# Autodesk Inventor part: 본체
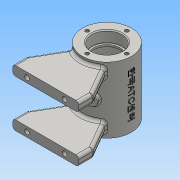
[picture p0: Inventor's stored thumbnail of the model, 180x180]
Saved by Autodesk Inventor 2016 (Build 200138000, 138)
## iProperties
Created: 2018-05
Part Number: 본체
Material: 일반
Document SubType Name: Modeling
Designer: Administrator
Density: 1 g/cm^3
Appearance: 기본값
Author: Administrator
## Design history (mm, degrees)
sketch "스케치1"
  geometry: L1 (0, 0)-(0, -70); L2 (0, 0)-(26, 0); L3 (26, 0)-(26, -70); L4 (26, -70)-(0, -70)
  constraints: 8 end point, 2 vertical, 1 horizontal
  dimensions: "d0" = 70 distance of L1.start L1.end; "d1" = 70 distance of L2.end L3.end; "d2" = 52 diameter of L3 L1
revolve "회전1" sketch "스케치1" stored, may be unused: angle "d3" = 90 deg
node "작업 평면1"
node "작업 평면2"
node "작업 평면3"
sketch "스케치2"
  geometry: L1 (0, 0)-(0, -103.85); L2 (-35, -65)-(35, -65); L3 (0, 0)-(20.203, 0); L4 (35, -65)-(35, -50); L5 (35, -50)-(17.325, -19.386); L6 (-35, -65)-(-35, -50); L7 (-35, -50)-(-17.325, -19.386); A1 r 26 centre (0, 0) between (17.325, -19.386) and (-17.325, -19.386) reference; A2 r 26 centre (0, 0) between (-17.325, -19.386) and (17.325, -19.386); 3 further points
  constraints: 14 end point, 4 point on circle, 3 vertical, 2 horizontal, 2 point on line, 1 centre point, 1 midpoint
  dimensions: "d8" = 65 vertical distance of L2.end L3.end; "d9" = 70 distance of L2.start L2.end; "d10" = 15 distance of L2.end L4.end; "d11" = 30 deg angle of L4 L5; "d12" = 15 distance of L2.start L6.end; "d13" = 30 deg angle of L6 L7
extrude "돌출1" join sketch "스케치2" distance "d14" = 10; taper "d15" = 0 deg
sketch "스케치3"
  geometry: L1 (0, 0)-(70, 0) reference; L2 (70, 0)-(70, 10) reference; L3 (0, 10)-(70, 10) reference; L4 (0, 0)-(0, 10) reference; L5 (9, 15)-(61, 15) reference; L6 (9, -55)-(61, -55) reference; L7 (0, -40)-(70, -40) reference; L8 (0, -50)-(70, -50) reference; L9 (35, 15)-(35, -55); L10 (55, 22.355)-(55, -60.469); L11 (15, 19.937)-(15, -63.895); L12 (77.307, 5)-(-12.167, 5); L13 (77.307, -45)-(-22.445, -45); C1 r 2.5 at (15, 5); C2 r 2.5 at (55, 5); C3 r 2.5 at (55, -45); C4 r 2.5 at (15, -45)
  constraints: 10 end point, 8 point on line, 4 centre point, 2 horizontal, 2 vertical, 1 midpoint
  dimensions: "d16" = 20 horizontal distance of L10.end L9.end; "d17" = 20 horizontal distance of L11.end L9.end; "d18" = 5 distance between parallel lines of L3 L12; "d19" = 5 distance between parallel lines of L8 L13; "d20" = 5 diameter of C1; "d21" = 5 diameter of C2; "d22" = 5 diameter of C3; "d23" = 5 diameter of C4
hole "구멍1" sketch "스케치3" at (15, 5), (55, 5), (55, -45), (15, -45) diameter "d24" = 5; stored, may be unused: countersink angle "d28" = 90 deg, drill point angle "d30" = 118 deg; dims "d25" = 6, "d26" = 4, "d27" = 2, "d29" = 10
feature "스레드1" dims "d31" = 8, "d32" = 0
feature "스레드2" dims "d33" = 8, "d34" = 0
feature "스레드3" dims "d35" = 8, "d36" = 0
feature "스레드4" dims "d37" = 8, "d38" = 0
node "작업 평면4"
sketch "스케치4"
  geometry: L1 (3.602, 24.887)-(3.602, -24.887); L2 (3.602, -24.887)-(-3.602, -24.887); L3 (-3.602, -24.887)-(-3.602, 24.887); L4 (-3.602, 24.887)-(3.602, 24.887); L5 (-19.386, -20)-(-19.386, -30) reference; L6 (-19.386, -30)-(-19.386, -30) reference; L7 (-19.386, -30)-(-19.386, -20) reference; L8 (-19.386, -20)-(-19.386, -20) reference; L9 (-19.386, 30)-(-19.386, 20) reference; L10 (-19.386, 20)-(-19.386, 20) reference; L11 (-19.386, 20)-(-19.386, 30) reference; L12 (-19.386, 30)-(-19.386, 30) reference; L13 (-26, 35)-(26, 35) reference; L14 (-26, -35)-(26, -35) reference; L15 (26, 35)-(26, -35) reference; L16 (26, 0)-(0, 0); L17 (-26, 35)-(-26, -35) reference; 1 further point
  constraints: 2 end point, 1 midpoint, 2 other
feature "엠보싱1" sketch "스케치4" dims "d8" = 65, "d9" = 70, "d10" = 15, "d11" = 30 deg, "d12" = 15, "d13" = 30 deg, "d39" = 0.5, "d40" = 0
node "작업 평면6"
  node "작업 평면5"
sketch "스케치5"
  geometry: L1 (-26, 35)-(-26, -35) reference; L2 (-26, -35)-(26, -35) reference; L3 (-26, 35)-(26, 35) reference; L4 (26, 35)-(26, -35) reference; L5 (0, -35)-(0, 0); C1 r 5 at (0, 0); 1 further point
  constraints: 2 end point, 1 centre point, 1 coincident, 1 midpoint
  dimensions: "d42" = 10 diameter of C1
extrude "돌출2" join sketch "스케치5" distance "d43" = 20; taper "d44" = 0 deg
node "작업 평면7"
sketch "스케치6"
  geometry: L1 (5, 29)-(-5, 29) reference; L2 (0, 29)-(0, -23.345); L3 (0, 0)-(-8.893, -24.432); L4 (-4.593, -29.207)-(-9.924, -27.267); L5 (-4.593, -29.207)-(-3.347, -25.784); L6 (-9.924, -27.267)-(-8.893, -24.432); A1 r 26 centre (0, 0) between (17.325, -19.386) and (-17.325, -19.386) reference; A2 r 26 centre (0, 0) between (-17.325, -19.386) and (17.325, -19.386) reference; 1 further point
  constraints: 10 end point, 3 point on circle, 1 midpoint, 1 perpendicular, 1 point on line, 1 vertical
  dimensions: "d47" = 20 deg angle of L2 L3; "d54" = 27.26656 vertical distance of L4.end point (0, 0); "d57" = 11.3474 diameter of L5 L3
revolve "회전2" sketch "스케치6" stored, may be unused: angle "d58" = 90 deg
node "작업 평면8"
sketch "스케치8"
  geometry: L1 (-15, 39)-(-15, 91) reference; L2 (55, 39)-(55, 91) reference; L3 (-15, 65)-(55, 65); L4 (-15, 81)-(-3.3, 81); L5 (-3, 80.7)-(-3, 79); L6 (-3, 79)-(-1, 79); L7 (-1, 79)-(-1, 83); L8 (2, 86)-(38, 86); L9 (55, 81)-(43.3, 81); L10 (43, 80.7)-(43, 79); L11 (43, 79)-(41, 79); L12 (41, 83)-(41, 79); A1 r 0.3 centre (-3.3, 80.7) between (-3, 80.7) and (-3.3, 81); A2 r 0.3 centre (43.3, 80.7) between (43.3, 81) and (43, 80.7); A3 r 3 centre (38, 83) between (41, 83) and (38, 86); A4 r 3 centre (2, 83) between (2, 86) and (-1, 83); 4 further points
  constraints: 20 end point, 10 point on line, 8 point on circle, 8 tangent, 4 centre point, 3 perpendicular, 3 vertical, 2 equal radius, 2 horizontal, 1 midpoint
  dimensions: "d59" = 12 distance of L4.start point (-3, 81); "d60" = 32 diameter of L4 L3; "d61" = 2 distance of L5.end L6.end; "d62" = 28 diameter of L6 L3; "d63" = 42 diameter of L8 L3; "d64" = 42 distance of point (-1, 86) point (41, 86); "d65" = 12 distance of L9.start point (43, 81); "d66" = 32 diameter of L9 L3; "d67" = 2 distance of L10.end L11.end; "d68" = 28 diameter of L11 L3; "d69" = 0.3 radius of A1; "d70" = 3 radius of A3
revolve "회전3" sketch "스케치8" stored, may be unused: angle "d71" = 90 deg
chamfer "모따기1" distance "d72" = 1; stored, may be unused: second distance "d73" = 2, angle "d74" = 45 deg
chamfer "모따기2" distance "d75" = 1; stored, may be unused: second distance "d76" = 2, angle "d77" = 45 deg
sketch "스케치9"
  geometry: C1 r 5.674 at (0, 0) reference; C2 r 3 at (0, 0); 1 further point
  constraints: 1 centre point, 1 coincident
  dimensions: "d78" = 6 diameter of C2
extrude "돌출3" cut sketch "스케치9" stored distance "d79" = 20; taper "d80" = 0 deg
sketch "스케치10"
  geometry: C1 r 5 at (0, 0) reference; C2 r 3 at (0, 0); 1 further point
  constraints: 1 centre point, 1 coincident
  dimensions: "d81" = 6 diameter of C2
extrude "돌출4" cut sketch "스케치10" stored distance "d82" = 20; taper "d83" = 0 deg
feature "스레드5" dims "d84" = 10, "d85" = 0
feature "스레드6" dims "d86" = 10, "d87" = 0
sketch "스케치11" dims "d88" = 42
  geometry: L1 (0, 0)-(-21, 0); C1 r 26 at (0, 0) reference; C2 r 2 at (-21, 0); 1 further point
  constraints: 2 coincident, 2 end point, 1 centre point, 1 horizontal, 1 horizontal alignment, 2 other
  dimensions: "d89" = 4 diameter of C2
hole "구멍2" sketch "스케치11" at (-21, 0) diameter "d90" = 4; stored, may be unused: countersink angle "d94" = 90 deg, drill point angle "d96" = 118 deg; dims "d91" = 6, "d92" = 4, "d93" = 2, "d95" = 10
node "작업 평면9"
feature "스레드7" dims "d100" = 8, "d101" = 0
feature "스레드8" dims "d102" = 8, "d103" = 0
feature "스레드9" dims "d104" = 8, "d105" = 0
feature "스레드10" dims "d106" = 8, "d107" = 0
feature "스레드11" dims "d108" = 8, "d109" = 0
feature "스레드12" dims "d110" = 8, "d111" = 0
feature "스레드13" dims "d112" = 8, "d113" = 0
feature "스레드14" dims "d114" = 8, "d115" = 0
fillet "모깎기3" dims "d118" = 3
fillet "모깎기4" dims "d119" = 2
fillet "모깎기5" dims "d120" = 2
node "솔리드1"
mirror "대칭1"
pattern_circular "원형 패턴1" dims angle "d98" = 360 deg
mirror "대칭2"
node "투영된 루프1"
node "투영된 루프2"
other parameters: "d41" = -3
